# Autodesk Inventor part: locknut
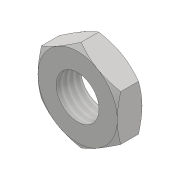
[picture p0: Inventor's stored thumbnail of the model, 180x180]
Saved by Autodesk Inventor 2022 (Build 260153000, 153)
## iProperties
Created: 2016-05
Part Number: locknut
Material: Generic
Document SubType Name: Modeling
Designer: CADCIM
Density: 1 g/cm^3
Appearance: Default
Author: CADCIM
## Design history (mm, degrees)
sketch "Sketch1"
  geometry: L1 (9.6, -5.543)-(0, -11.085); L2 (0, -11.085)-(-9.6, -5.543); L3 (-9.6, -5.543)-(-9.6, 5.543); L4 (-9.6, 5.543)-(0, 11.085); L5 (0, 11.085)-(9.6, 5.543); L6 (9.6, 5.543)-(9.6, -5.543); 2 further points
  constraints: 12 end point, 1 coincident, 1 vertical alignment, 13 other
  dimensions: "d0" = 19.2 distance between parallel lines of L3 L6
extrude "Extrusion1" new body sketch "Sketch1" distance "d1" = 6; taper "d2" = 0 deg
sketch "Sketch2"
  geometry: L1 (0, 11.085)-(-9.6, 5.543) reference; C1 r 9.6 at (0, 0); 1 further point
  constraints: 1 centre point, 1 coincident, 1 tangent
extrude "Extrusion2" sketch "Sketch2" distance "d3" = 10.8; taper "d4" = 60 deg
workplane "Work Plane1"
sketch "Sketch3"
  geometry: L1 (0, -11.085)-(9.6, -5.543) reference; C1 r 9.6 at (0, 0); 1 further point
  constraints: 1 centre point, 1 coincident, 1 tangent
extrude "Extrusion3" sketch "Sketch3" distance "d5" = 10.8; taper "d6" = 60 deg
sketch "Sketch4"
  geometry: 1 further point
hole "Hole1" diameter "d9" = 10.376; stored, may be unused: countersink angle "d13" = 90 deg, drill point angle "d15" = 118 deg; dims "d7" = 10, "d8" = 10, "d10" = 24, "d11" = 4, "d12" = 2, "d14" = 31.3
body "Solid1"
